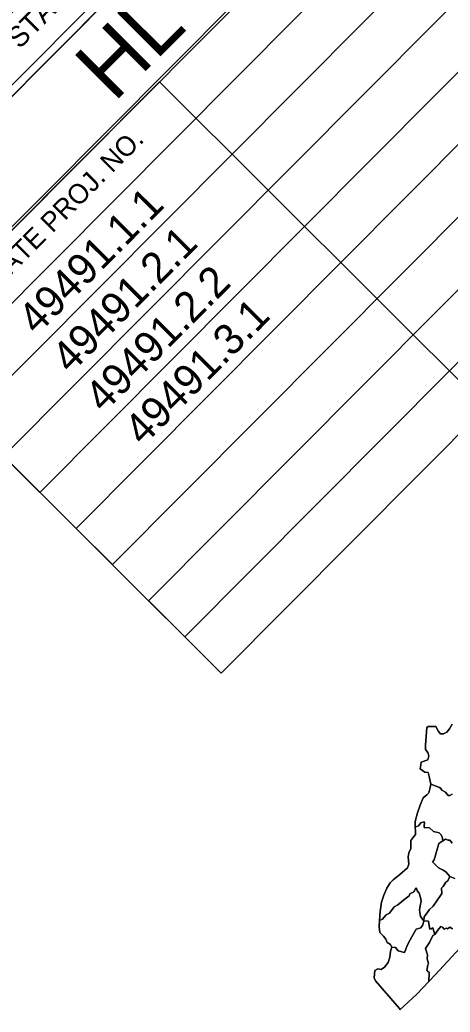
# Model space of a CAD drawing. Extents: x 1481763 to 1495577, y 493394 to 506245.
# Drawn here: x 1488088 to 1488403, y 500209 to 500935 of the extents above; entities that cross this region are included whole.
import ezdxf

# ---------------------------------------------------------------- set-up
doc = ezdxf.new("R2010")
doc.units = 0
for name, color, linetype in [('Old_Level_20', 7, 'Continuous'), ('Sheet Cutting Line CELL', 7, 'Continuous'), ('Sheet Data Field CELL', 7, 'Continuous'), ('Sheet Plot Border Inside CELL', 7, 'Continuous'), ('Sheet Title CELL', 7, 'Continuous')]:
    doc.layers.add(name, color=color, linetype=linetype)

msp = doc.modelspace()

# ---------------------------------------------------------------- linework, layer by layer
at = {"layer": 'Old_Level_20'}
for points in [[(1488404.67, 500419.35), (1488402.77, 500415.97), (1488400.7, 500413.49), (1488398.21, 500412.21), (1488396.19, 500412.34), (1488394.56, 500413.99), (1488392.59, 500417.62), (1488387.07, 500417.75), (1488385.99, 500416.9), (1488385.04, 500404.07), (1488385.11, 500400.85), (1488386.78, 500398.72), (1488387.43, 500396.12), (1488386.87, 500393.27), (1488382.01, 500391.67), (1488381.75, 500389.56), (1488381.28, 500386.6), (1488384.57, 500384.2), (1488386.97, 500384.03), (1488387.67, 500381.14), (1488389, 500375.46), (1488388.6, 500373.08)], [(1488385.04, 500404.07), (1488385.99, 500416.9), (1488387.07, 500417.75), (1488392.59, 500417.62), (1488394.56, 500413.99), (1488396.19, 500412.34), (1488398.21, 500412.21), (1488400.7, 500413.49), (1488402.77, 500415.97), (1488404.67, 500419.35)], [(1488404.71, 500368.11), (1488402.85, 500367.15), (1488401.79, 500367.17), (1488399.68, 500369.63), (1488396.97, 500371.1), (1488396.35, 500372.33), (1488395.46, 500373.01), (1488389, 500375.46), (1488387.67, 500381.14), (1488386.97, 500384.03), (1488384.57, 500384.2), (1488381.28, 500386.6), (1488381.75, 500389.56), (1488382.01, 500391.67), (1488386.87, 500393.27), (1488387.43, 500396.12), (1488386.78, 500398.72), (1488385.11, 500400.85), (1488385.04, 500404.07)], [(1488404.53, 500332.36), (1488402.86, 500334.47), (1488401.69, 500334.4), (1488399.86, 500335.18), (1488397.69, 500333.96), (1488397.27, 500336.9), (1488396.23, 500338.66), (1488395.13, 500339.84), (1488390.98, 500340.68), (1488388.04, 500343.51), (1488384.12, 500343.83), (1488384.07, 500345), (1488384.43, 500347.18), (1488384.12, 500347.8), (1488381.72, 500347.09), (1488380.02, 500345.04), (1488377.56, 500343.95), (1488377.5, 500348.22), (1488379.34, 500354.51), (1488381.19, 500360.12), (1488383.29, 500365.42), (1488385.98, 500367.55), (1488387.64, 500369.21), (1488388.6, 500373.08), (1488389, 500375.46)], [(1488389, 500375.46), (1488395.46, 500373.01), (1488396.35, 500372.33), (1488396.97, 500371.1), (1488399.68, 500369.63), (1488401.79, 500367.17), (1488402.85, 500367.15), (1488404.71, 500368.11)], [(1488388.6, 500373.08), (1488387.64, 500369.21), (1488385.98, 500367.55), (1488383.29, 500365.42), (1488381.19, 500360.12), (1488379.34, 500354.51), (1488377.5, 500348.22), (1488377.56, 500343.95), (1488377.79, 500341.02), (1488377.79, 500338.6), (1488375.85, 500336.19), (1488374.26, 500334.23), (1488374.3, 500331.33), (1488374.31, 500328.23), (1488372.78, 500325.1), (1488372.33, 500322.15), (1488372.95, 500316.78), (1488371.97, 500314.27), (1488366.17, 500309.26), (1488361.48, 500305.5), (1488359.2, 500303.31), (1488356.7, 500299.22), (1488354.47, 500294.14), (1488352.73, 500289.1), (1488351.84, 500282.14), (1488351.37, 500275.53), (1488351.04, 500270.94), (1488351.62, 500266.74), (1488354.32, 500264.25), (1488356.09, 500262.06), (1488356.95, 500259.47), (1488359.49, 500258.06), (1488360.33, 500256.15), (1488359.52, 500253.25), (1488358.84, 500248.89), (1488357.63, 500244.97), (1488355.13, 500241.56), (1488352.54, 500239.79), (1488350.17, 500240.12), (1488347.93, 500238.99), (1488347.43, 500233.55), (1488348.53, 500231.33), (1488366.15, 500211.12), (1488366.23, 500210.16), (1488378.71, 500221.69), (1488387.6, 500230.98), (1488392.26, 500235.79), (1488416.66, 500262.17)], [(1488378.11, 500299.34), (1488376.55, 500296.71), (1488373.68, 500295.27), (1488373.21, 500293.68), (1488370.25, 500291.47), (1488364.75, 500287.21), (1488362.08, 500285.74), (1488358.65, 500281.07), (1488356.27, 500279.67), (1488354.53, 500277.92), (1488353.51, 500276.57), (1488351.37, 500275.53), (1488351.84, 500282.14), (1488352.73, 500289.1), (1488354.47, 500294.14), (1488356.7, 500299.22), (1488359.2, 500303.31), (1488361.48, 500305.5), (1488366.17, 500309.26), (1488371.97, 500314.27), (1488372.95, 500316.78), (1488372.33, 500322.15), (1488372.78, 500325.1), (1488374.31, 500328.23), (1488374.3, 500331.33), (1488374.26, 500334.23), (1488375.85, 500336.19), (1488377.79, 500338.6), (1488377.79, 500341.02), (1488377.56, 500343.95), (1488380.02, 500345.04), (1488381.72, 500347.09), (1488384.12, 500347.8), (1488384.43, 500347.18), (1488384.07, 500345), (1488384.12, 500343.83), (1488388.04, 500343.51), (1488390.98, 500340.68), (1488395.13, 500339.84), (1488396.23, 500338.66), (1488397.27, 500336.9), (1488397.69, 500333.96), (1488394.85, 500332.04), (1488391.57, 500320.13), (1488390.33, 500318.62), (1488394.63, 500314.3), (1488398.16, 500312.48), (1488400.03, 500311.22), (1488402.98, 500307.73), (1488401.37, 500304.72), (1488399.99, 500303.62), (1488398.08, 500300.54), (1488396.86, 500299.22), (1488397.17, 500295.34), (1488396.04, 500293.92), (1488390.7, 500286.19), (1488388.01, 500283.68), (1488385.68, 500280.26), (1488384.21, 500278.39), (1488383.78, 500275.45), (1488381.53, 500278.47), (1488381.08, 500280.34), (1488380.65, 500283.28), (1488381.3, 500286.39), (1488382, 500289.88), (1488381.53, 500292.44), (1488380.37, 500295.64), (1488379.03, 500297.32), (1488378.49, 500299.3), (1488378.11, 500299.34)], [(1488406.58, 500306.48), (1488402.98, 500307.73), (1488400.03, 500311.22), (1488398.16, 500312.48), (1488394.63, 500314.3), (1488390.33, 500318.62), (1488391.57, 500320.13), (1488394.85, 500332.04)], [(1488394.85, 500332.04), (1488397.69, 500333.96), (1488399.86, 500335.18), (1488401.69, 500334.4), (1488402.86, 500334.47), (1488404.53, 500332.36)], [(1488404.79, 500269.64), (1488403.01, 500270.78), (1488401.34, 500269.61), (1488400.22, 500269.92), (1488398.7, 500269.21), (1488397.55, 500270.86), (1488396.43, 500271.17), (1488394.02, 500268.54), (1488391.91, 500265.29), (1488391.25, 500267.86), (1488390.46, 500270.15), (1488389.13, 500269.42), (1488388.34, 500269.31), (1488387.99, 500270.4), (1488387.19, 500275.1), (1488383.78, 500275.45), (1488384.21, 500278.39), (1488385.68, 500280.26), (1488388.01, 500283.68), (1488390.7, 500286.19), (1488396.04, 500293.92), (1488397.17, 500295.34), (1488396.86, 500299.22), (1488398.08, 500300.54), (1488399.99, 500303.62), (1488401.37, 500304.72)], [(1488401.37, 500304.72), (1488402.98, 500307.73), (1488406.58, 500306.48)], [(1488383.78, 500275.45), (1488383.04, 500272.44), (1488381.74, 500270.36), (1488378.26, 500269.27), (1488372.94, 500259.8), (1488371.33, 500256.6), (1488370.63, 500254.65), (1488369.59, 500252.25), (1488365.11, 500253.46), (1488363.07, 500255.78), (1488360.33, 500256.15), (1488359.49, 500258.06), (1488356.95, 500259.47), (1488356.09, 500262.06), (1488354.32, 500264.25), (1488351.62, 500266.74), (1488351.04, 500270.94), (1488351.37, 500275.53), (1488353.51, 500276.57), (1488354.53, 500277.92), (1488356.27, 500279.67), (1488358.65, 500281.07), (1488362.08, 500285.74), (1488364.75, 500287.21), (1488370.25, 500291.47), (1488373.21, 500293.68), (1488373.68, 500295.27), (1488376.55, 500296.71), (1488378.11, 500299.34), (1488378.49, 500299.3), (1488379.03, 500297.32), (1488380.37, 500295.64), (1488381.53, 500292.44), (1488382, 500289.88), (1488381.3, 500286.39), (1488380.65, 500283.28), (1488381.08, 500280.34), (1488381.53, 500278.47), (1488383.78, 500275.45)], [(1488383.78, 500275.45), (1488387.19, 500275.1), (1488387.99, 500270.4), (1488388.34, 500269.31), (1488389.13, 500269.42), (1488390.46, 500270.15), (1488391.25, 500267.86), (1488391.91, 500265.29), (1488390.49, 500264.67), (1488388.09, 500259.63), (1488385.18, 500255.21), (1488386.45, 500250.38), (1488386.23, 500247.62), (1488387.27, 500244.15), (1488386.76, 500243.05), (1488386.02, 500239), (1488386.54, 500238.56), (1488387.76, 500237.48), (1488387.6, 500230.98), (1488378.71, 500221.69), (1488366.23, 500210.16), (1488366.15, 500211.12), (1488348.53, 500231.33), (1488347.43, 500233.55), (1488347.93, 500238.99), (1488350.17, 500240.12), (1488352.54, 500239.79), (1488355.13, 500241.56), (1488357.63, 500244.97), (1488358.84, 500248.89), (1488359.52, 500253.25), (1488360.33, 500256.15), (1488363.07, 500255.78), (1488365.11, 500253.46), (1488369.59, 500252.25), (1488370.63, 500254.65), (1488371.33, 500256.6), (1488372.94, 500259.8), (1488378.26, 500269.27), (1488381.74, 500270.36), (1488383.04, 500272.44), (1488383.78, 500275.45)], [(1488416.66, 500262.17), (1488392.26, 500235.79), (1488387.6, 500230.98), (1488387.76, 500237.48), (1488386.54, 500238.56), (1488386.02, 500239), (1488386.76, 500243.05), (1488387.27, 500244.15), (1488386.23, 500247.62), (1488386.45, 500250.38), (1488385.18, 500255.21), (1488388.09, 500259.63), (1488390.49, 500264.67), (1488391.91, 500265.29), (1488394.02, 500268.54), (1488396.43, 500271.17)], [(1488396.43, 500271.17), (1488397.55, 500270.86), (1488398.7, 500269.21), (1488400.22, 500269.92), (1488401.34, 500269.61), (1488403.01, 500270.78), (1488404.79, 500269.64)]]:
    msp.add_lwpolyline(points, dxfattribs=at)
at = {"layer": 'Sheet Cutting Line CELL'}
msp.add_line((1485019.38, 497803.89), (1488584.25, 501383.61), dxfattribs=at)
msp.add_lwpolyline([(1485019.38, 497803.89), (1488584.25, 501383.61), (1490922.52, 499055.04), (1487357.65, 495475.32)], close=True, dxfattribs=at)
at = {"layer": 'Sheet Plot Border Inside CELL'}
msp.add_lwpolyline([(1487337.48, 495550.45), (1490865.3, 499092.97), (1488622.45, 501326.52), (1485094.62, 497784)], close=True, dxfattribs=at)
at = {"layer": 'Sheet Title CELL'}
for points in [[(1487942.92, 500747.89), (1488525.07, 501332.47), (1488498.5, 501358.93), (1487916.37, 500774.33), (1488235.21, 500456.82), (1488429.25, 500651.61), (1488190.1, 500889.77), (1488075.47, 500774.66)], [(1488022.66, 500668.48), (1488604.81, 501253.06), (1488578.21, 501279.54), (1487996.06, 500694.97)], [(1488235.21, 500456.82), (1488817.36, 501041.39), (1488790.81, 501067.83), (1488208.64, 500483.28), (1488182.09, 500509.71), (1488764.24, 501094.29), (1488737.67, 501120.75), (1488155.55, 500536.2), (1488128.92, 500562.66), (1488711.07, 501147.24), (1488684.5, 501173.7), (1488102.35, 500589.12), (1488075.8, 500615.56), (1488657.93, 501200.16), (1488631.38, 501226.6), (1488049.23, 500642.02)]]:
    msp.add_lwpolyline(points, dxfattribs=at)

# ---------------------------------------------------------------- texts
at = {"layer": 'Sheet Data Field CELL'}
for s, height, p in [('HL-0025', 45, (1488156.75, 500874.13)), ('49491.1.1', 22.5, (1488100.23, 500703.65)), ('49491.2.1', 22.5, (1488124.9, 500675.28)), ('49491.2.2', 22.5, (1488149.2, 500646.53)), ('49491.3.1', 22.5, (1488178.02, 500622.38))]:
    msp.add_text(s, height=height, rotation=45.11911, dxfattribs=at).set_placement(p)
at = {"layer": 'Sheet Title CELL'}
for s, height, p in [('STATE PROJECT REFERENCE NO.', 14.9994, (1488087.6, 500913.31)), ('STATE PROJ. NO.', 14.4, (1488064.08, 500730.75))]:
    msp.add_text(s, height=height, rotation=45.11911, dxfattribs=at).set_placement(p)

doc.saveas('drawing.dxf')
